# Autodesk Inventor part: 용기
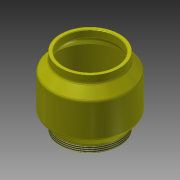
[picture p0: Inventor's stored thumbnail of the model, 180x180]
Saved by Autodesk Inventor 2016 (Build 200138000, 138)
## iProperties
Created: 2018-01
Part Number: 용기
Material: ABS 플라스틱
Document SubType Name: Modeling
Designer: mduedu
Density: 1 g/cm^3
Appearance: 노란색
Author: mduedu
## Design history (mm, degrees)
sketch "스케치1"
  geometry: L1 (0, 0)-(-35, 0); L2 (-35, 0)-(-35, 9); L3 (-35, 9)-(-45, 20); L4 (-45, 20)-(-45, 60); L5 (-45, 60)-(-35, 71); L6 (-35, 71)-(-35, 80); L7 (-35, 80)-(0, 80); L8 (0, 80)-(0, 0)
  constraints: 16 end point, 3 collinear, 3 parallel, 1 horizontal, 1 perpendicular
  dimensions: "d0" = 9 distance of L1.end L2.end; "d2" = 70 diameter of L2 L8; "d3" = 20 distance from line of L3.end L1; "d4" = 60 distance from line of L4.end L1; "d5" = 20 distance from line of L4.end L7; "d6" = 90 diameter of L4 L8
revolve "회전1" sketch "스케치1" stored, may be unused: angle "d7" = 90 deg
fillet "모깎기1" dims "d8" = 3
feature "쉘1" dims "d9" = 4
chamfer "모따기1" distance "d11" = 0.5; stored, may be unused: second distance "d12" = 2, angle "d13" = 45 deg
feature "스레드1" dims "d14" = 7, "d15" = 0
node "솔리드1"
